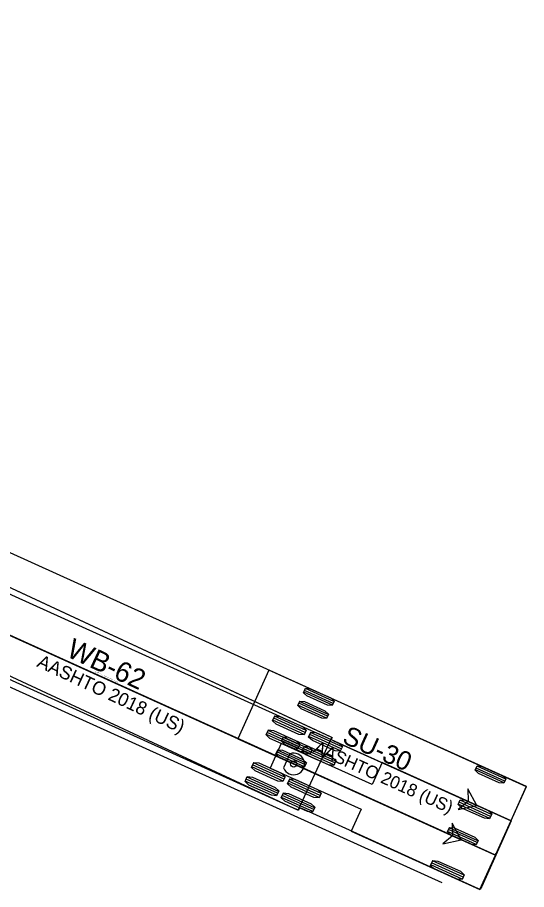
# Model space of a CAD drawing. Extents: x 186128 to 186702, y 352195 to 353183.
# Drawn here: x 186387.2 to 186441.3, y 352346 to 352438.5 of the extents above; entities that cross this region are included whole.
import ezdxf

# ---------------------------------------------------------------- set-up
doc = ezdxf.new("R2010")
doc.units = 0
doc.layers.add('SV_X_Control_Cells_Found', color=7, linetype='Continuous')
doc.layers.add('SV_X_Shot_Marker', color=7, linetype='Continuous')

msp = doc.modelspace()

# ---------------------------------------------------------------- linework, layer by layer
at = {"layer": 'SV_X_Control_Cells_Found'}
for p, q in [((186248.916, 352439.53), (186435.98, 352354.924)), ((186413.939, 352369.283), (186410.642, 352361.994)), ((186441.273, 352356.92), (186413.939, 352369.283)), ((186420.667, 352365.554), (186417.629, 352366.928)), ((186420.752, 352365.744), (186417.715, 352367.118)), ((186420.838, 352365.934), (186417.801, 352367.308)), ((186420.22, 352364.567), (186417.183, 352365.941)), ((186420.048, 352364.188), (186417.011, 352365.561)), ((186420.134, 352364.377), (186417.097, 352365.751)), ((186410.642, 352361.994), (186437.976, 352349.631)), ((186418.331, 352360.391), (186415.294, 352361.765)), ((186418.417, 352360.581), (186415.38, 352361.955)), ((186418.503, 352360.771), (186415.466, 352362.145)), ((186417.713, 352359.024), (186414.676, 352360.398)), ((186417.799, 352359.214), (186414.762, 352360.588)), ((186417.885, 352359.404), (186414.848, 352360.778)), ((186438.889, 352357.312), (186435.852, 352358.686)), ((186438.975, 352357.502), (186435.938, 352358.876)), ((186439.061, 352357.692), (186436.024, 352359.065)), ((186437.976, 352349.631), (186441.273, 352356.92)), ((186441.273, 352356.92), (186441.273, 352356.92)), ((186435.936, 352350.782), (186432.899, 352352.156)), ((186436.022, 352350.972), (186432.985, 352352.346)), ((186436.107, 352351.162), (186433.07, 352352.536))]:
    msp.add_line(p, q, dxfattribs=at)
for points in [[(186383.993, 352382.833), (186384.157, 352382.767), (186441.243, 352356.914), (186438.127, 352349.959), (186437.897, 352349.664), (186348.921, 352389.952), (186302.3, 352410.917), (186273.593, 352423.482), (186264.341, 352427.288), (186263.98, 352427.518), (186248.199, 352433.916), (186245.574, 352435.097), (186242.72, 352436.606), (186240.03, 352438.312), (186238.324, 352439.526)], [(186420.86, 352365.981), (186420.645, 352365.507), (186420.156, 352365.557), (186417.969, 352366.546), (186417.608, 352366.881), (186417.822, 352367.355), (186418.312, 352367.305), (186420.499, 352366.316), (186420.86, 352365.981)], [(186420.241, 352364.614), (186420.027, 352364.14), (186419.537, 352364.19), (186417.351, 352365.179), (186416.99, 352365.514), (186417.204, 352365.988), (186417.694, 352365.938), (186419.881, 352364.949), (186420.241, 352364.614)], [(186418.524, 352360.818), (186418.31, 352360.344), (186417.82, 352360.394), (186415.633, 352361.383), (186415.273, 352361.718), (186415.487, 352362.192), (186415.977, 352362.142), (186418.164, 352361.153), (186418.524, 352360.818)], [(186417.906, 352359.451), (186417.692, 352358.977), (186417.202, 352359.027), (186415.015, 352360.016), (186414.655, 352360.351), (186414.869, 352360.825), (186415.359, 352360.775), (186417.545, 352359.786), (186417.906, 352359.451)], [(186439.082, 352357.739), (186438.868, 352357.265), (186438.378, 352357.314), (186436.191, 352358.304), (186435.831, 352358.639), (186436.045, 352359.112), (186436.535, 352359.063), (186438.722, 352358.074), (186439.082, 352357.739)], [(186435.98, 352354.924), (186435.036, 352356.687), (186435.069, 352355.336), (186434.032, 352354.468), (186435.98, 352354.924)], [(186436.129, 352351.209), (186435.914, 352350.735), (186435.425, 352350.785), (186433.238, 352351.774), (186432.877, 352352.109), (186433.092, 352352.583), (186433.581, 352352.533), (186435.768, 352351.544), (186436.129, 352351.209)]]:
    msp.add_lwpolyline(points, dxfattribs=at)
msp.add_lwpolyline([(186435.98, 352354.924), (186435.036, 352356.687), (186435.069, 352355.336), (186434.032, 352354.468)], close=True, dxfattribs=at)
msp.add_circle((186435.98, 352354.924), 0.0417, dxfattribs=at)
at = {"layer": 'SV_X_Shot_Marker'}
for p, q in [((186292.856, 352415.266), (186434.331, 352351.279)), ((186313.666, 352400.367), (186432.271, 352346.724)), ((186420.625, 352362.112), (186377.111, 352382.376)), ((186373.523, 352374.67), (186417.036, 352354.407)), ((186417.781, 352362.652), (186414.44, 352364.163)), ((186417.875, 352362.861), (186414.534, 352364.372)), ((186417.686, 352362.443), (186414.345, 352363.954)), ((186417.006, 352360.94), (186413.665, 352362.451)), ((186417.101, 352361.148), (186413.76, 352362.659)), ((186417.195, 352361.357), (186413.854, 352362.868)), ((186421.607, 352360.921), (186418.267, 352362.432)), ((186421.702, 352361.13), (186418.361, 352362.641)), ((186415.241, 352361.486), (186414.06, 352358.874)), ((186424.899, 352357.118), (186415.241, 352361.486)), ((186417.036, 352354.407), (186420.625, 352362.112)), ((186421.513, 352360.712), (186418.172, 352362.223)), ((186420.625, 352362.112), (186420.625, 352362.112)), ((186416.161, 352360.384), (186415.495, 352358.912)), ((186420.833, 352359.209), (186417.492, 352360.72)), ((186420.927, 352359.418), (186417.587, 352360.929)), ((186421.022, 352359.626), (186417.681, 352361.137)), ((186425.957, 352359.457), (186424.899, 352357.118)), ((186439.624, 352353.275), (186425.957, 352359.457)), ((186415.447, 352357.492), (186412.106, 352359.003)), ((186415.542, 352357.701), (186412.201, 352359.212)), ((186415.636, 352357.91), (186412.295, 352359.421)), ((186414.06, 352358.874), (186423.718, 352354.506)), ((186414.862, 352356.198), (186411.521, 352357.709)), ((186414.956, 352356.407), (186411.615, 352357.918)), ((186419.463, 352356.179), (186416.122, 352357.69)), ((186414.767, 352355.989), (186411.426, 352357.5)), ((186419.274, 352355.762), (186415.933, 352357.273)), ((186419.368, 352355.97), (186416.028, 352357.481)), ((186418.594, 352354.258), (186415.253, 352355.769)), ((186418.688, 352354.467), (186415.348, 352355.978)), ((186418.783, 352354.676), (186415.442, 352356.187)), ((186437.367, 352353.542), (186434.026, 352355.053)), ((186437.461, 352353.751), (186434.12, 352355.262)), ((186437.556, 352353.959), (186434.215, 352355.47)), ((186423.718, 352354.506), (186422.66, 352352.168)), ((186436.328, 352345.986), (186439.624, 352353.275)), ((186439.624, 352353.275), (186439.624, 352353.275)), ((186422.66, 352352.168), (186436.328, 352345.986)), ((186434.448, 352347.088), (186431.107, 352348.599)), ((186434.542, 352347.297), (186431.202, 352348.808)), ((186434.637, 352347.506), (186431.296, 352349.017))]:
    msp.add_line(p, q, dxfattribs=at)
for points in [[(186385.927, 352378.27), (186386.091, 352378.204), (186420.441, 352362.226), (186420.638, 352362.128), (186420.539, 352361.898), (186420.802, 352361.767), (186439.634, 352353.27), (186436.517, 352346.314), (186436.353, 352346.019), (186436.189, 352346.052), (186417.423, 352354.582), (186417.193, 352354.648), (186417.062, 352354.418), (186416.209, 352354.779), (186381.005, 352370.724), (186379.595, 352371.282), (186372.541, 352374.53), (186333.105, 352392.181), (186307.383, 352403.532)], [(186417.898, 352362.912), (186417.663, 352362.391), (186417.124, 352362.446), (186414.719, 352363.534), (186414.322, 352363.902), (186414.558, 352364.423), (186415.096, 352364.369), (186417.502, 352363.281), (186417.898, 352362.912)], [(186417.218, 352361.409), (186416.983, 352360.888), (186416.444, 352360.942), (186414.039, 352362.03), (186413.642, 352362.399), (186413.878, 352362.92), (186414.416, 352362.865), (186416.822, 352361.777), (186417.218, 352361.409)], [(186421.725, 352361.182), (186421.49, 352360.66), (186420.951, 352360.715), (186418.545, 352361.803), (186418.149, 352362.171), (186418.384, 352362.693), (186418.923, 352362.638), (186421.329, 352361.55), (186421.725, 352361.182)], [(186421.045, 352359.678), (186420.81, 352359.157), (186420.271, 352359.212), (186417.865, 352360.299), (186417.469, 352360.668), (186417.704, 352361.189), (186418.243, 352361.135), (186420.649, 352360.047), (186421.045, 352359.678)], [(186415.659, 352357.962), (186415.424, 352357.441), (186414.885, 352357.495), (186412.48, 352358.583), (186412.083, 352358.952), (186412.319, 352359.473), (186412.857, 352359.418), (186415.263, 352358.33), (186415.659, 352357.962)], [(186414.979, 352356.458), (186414.744, 352355.937), (186414.205, 352355.992), (186411.8, 352357.08), (186411.403, 352357.448), (186411.639, 352357.969), (186412.177, 352357.915), (186414.583, 352356.827), (186414.979, 352356.458)], [(186419.486, 352356.231), (186419.251, 352355.71), (186418.712, 352355.764), (186416.306, 352356.852), (186415.91, 352357.221), (186416.145, 352357.742), (186416.684, 352357.687), (186419.09, 352356.6), (186419.486, 352356.231)], [(186418.806, 352354.728), (186418.571, 352354.206), (186418.032, 352354.261), (186415.626, 352355.349), (186415.23, 352355.717), (186415.465, 352356.239), (186416.004, 352356.184), (186418.41, 352355.096), (186418.806, 352354.728)], [(186437.579, 352354.011), (186437.343, 352353.49), (186436.805, 352353.545), (186434.399, 352354.633), (186434.003, 352355.001), (186434.238, 352355.522), (186434.777, 352355.468), (186437.182, 352354.38), (186437.579, 352354.011)], [(186434.331, 352351.279), (186433.387, 352353.042), (186433.42, 352351.691), (186432.384, 352350.824), (186434.331, 352351.279)], [(186434.66, 352347.557), (186434.425, 352347.036), (186433.886, 352347.091), (186431.48, 352348.179), (186431.084, 352348.547), (186431.319, 352349.068), (186431.858, 352349.014), (186434.264, 352347.926), (186434.66, 352347.557)]]:
    msp.add_lwpolyline(points, dxfattribs=at)
msp.add_lwpolyline([(186434.331, 352351.279), (186433.387, 352353.042), (186433.42, 352351.691), (186432.384, 352350.824)], close=True, dxfattribs=at)
for centre, radius in [((186416.564, 352359.315), 0.34), ((186434.331, 352351.279), 0.0417)]:
    msp.add_circle(centre, radius, dxfattribs=at)
msp.add_arc((186416.564, 352359.315), 1.143, 200.66414, 110.66414, dxfattribs=at)

# ---------------------------------------------------------------- texts
at = {"layer": 'SV_X_Control_Cells_Found'}
for s, height, p in [('SU-30', 2, (186421.598, 352361.604)), ('AASHTO 2018 (US)', 1.33333, (186418.557, 352360.602)), ('(c) 2025 Transoft Solutions, Inc. All rights reserved.', 0.08, (186424.448, 352360.096))]:
    msp.add_text(s, height=height, rotation=335.66238, dxfattribs=at).set_placement(p)
at = {"layer": 'SV_X_Shot_Marker'}
for s, height, p in [('WB-62', 2.125, (186392.33, 352370.788)), ('AASHTO 2018 (US)', 1.41667, (186389.225, 352369.694)), ('(c) 2025 Transoft Solutions, Inc. All rights reserved.', 0.085, (186395.478, 352369.087))]:
    msp.add_text(s, height=height, rotation=335.02933, dxfattribs=at).set_placement(p)

doc.saveas('drawing.dxf')
